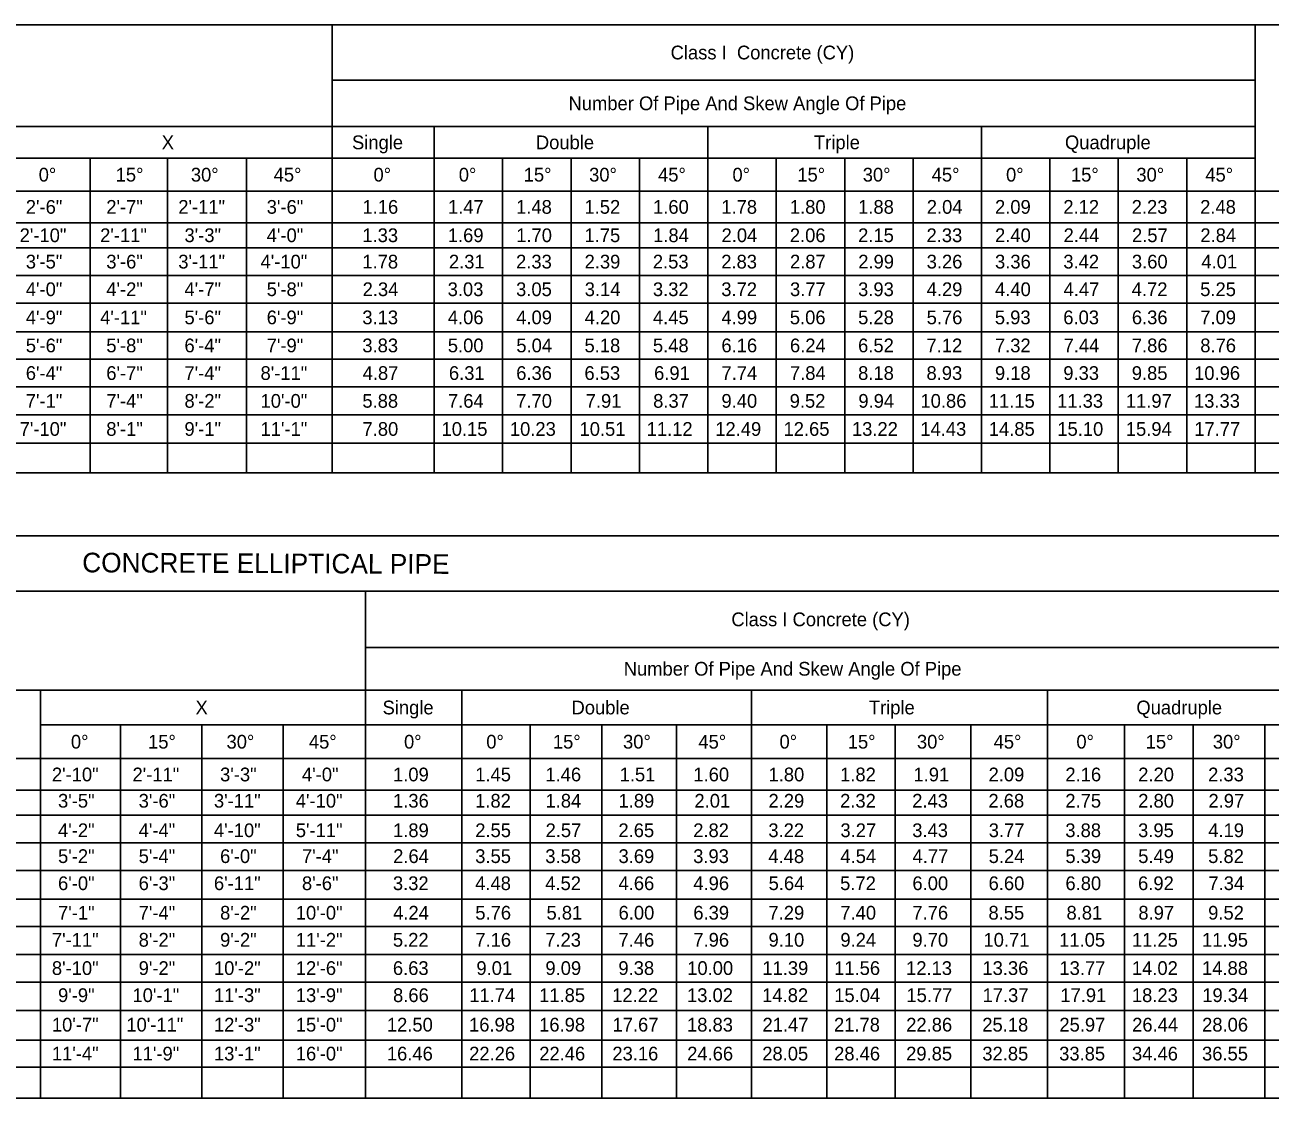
# Model space of a CAD drawing. Extents: x 10029 to 10796, y 10063 to 10519.
# Drawn here: x 10299.4 to 10616.8, y 10063.2 to 10336.7 of the extents above; entities that cross this region are included whole.
import ezdxf

# ---------------------------------------------------------------- set-up
doc = ezdxf.new("R2010")
doc.units = 0
doc.layers.add('Default', color=7, linetype='Continuous')
doc.layers.add('TextStructures', color=7, linetype='Continuous')

msp = doc.modelspace()

# ---------------------------------------------------------------- linework, layer by layer
at = {"layer": 'Default'}
for p, q in [((10039.72, 10336.74), (10681.45, 10336.74)), ((10377.67, 10222.58), (10377.67, 10336.74)), ((10612.98, 10222.58), (10612.98, 10336.74)), ((10377.67, 10322.67), (10612.98, 10322.67)), ((10079.67, 10310.85), (10612.98, 10310.85)), ((10403.72, 10222.58), (10403.72, 10310.85)), ((10473.47, 10222.58), (10473.47, 10310.85)), ((10543.23, 10222.58), (10543.23, 10310.85)), ((10294.71, 10302.76), (10612.98, 10302.76)), ((10315.99, 10222.58), (10315.99, 10302.76)), ((10335.73, 10222.58), (10335.73, 10302.76)), ((10355.84, 10222.58), (10355.84, 10302.76)), ((10421.16, 10222.58), (10421.16, 10302.76)), ((10438.6, 10222.58), (10438.6, 10302.76)), ((10456.04, 10222.58), (10456.04, 10302.76)), ((10490.91, 10222.58), (10490.91, 10302.76)), ((10508.35, 10222.58), (10508.35, 10302.76)), ((10525.79, 10222.58), (10525.79, 10302.76)), ((10560.67, 10222.58), (10560.67, 10302.76)), ((10578.1, 10222.58), (10578.1, 10302.76)), ((10595.54, 10222.58), (10595.54, 10302.76)), ((10039.72, 10294.39), (10681.45, 10294.39)), ((10039.72, 10286.34), (10681.45, 10286.34)), ((10039.72, 10279.92), (10681.45, 10279.92)), ((10039.72, 10272.9), (10681.45, 10272.9)), ((10039.72, 10265.84), (10681.45, 10265.84)), ((10039.72, 10258.56), (10681.45, 10258.56)), ((10039.72, 10251.55), (10681.45, 10251.55)), ((10039.72, 10244.47), (10681.45, 10244.47)), ((10039.72, 10237.36), (10681.45, 10237.36)), ((10039.72, 10230.15), (10681.45, 10230.15)), ((10039.72, 10222.58), (10681.45, 10222.58)), ((10040.76, 10206.56), (10696.75, 10206.56)), ((10040.76, 10192.44), (10696.75, 10192.44)), ((10386.23, 10063.22), (10386.23, 10192.44)), ((10386.23, 10178.05), (10632.55, 10178.05)), ((10084.96, 10167.22), (10632.55, 10167.22)), ((10303.39, 10063.22), (10303.39, 10167.22)), ((10410.73, 10063.22), (10410.73, 10167.22)), ((10484.61, 10063.22), (10484.61, 10167.22)), ((10560.04, 10063.22), (10560.04, 10167.22)), ((10303.39, 10158.32), (10632.55, 10158.32)), ((10323.73, 10063.22), (10323.73, 10158.32)), ((10344.5, 10063.22), (10344.5, 10158.32)), ((10365.25, 10063.22), (10365.25, 10158.32)), ((10428.17, 10063.22), (10428.17, 10158.32)), ((10446.47, 10063.22), (10446.47, 10158.32)), ((10465.46, 10063.22), (10465.46, 10158.32)), ((10503.77, 10063.22), (10503.77, 10158.32)), ((10521.21, 10063.22), (10521.21, 10158.32)), ((10540.54, 10063.22), (10540.54, 10158.32)), ((10579.72, 10063.22), (10579.72, 10158.32)), ((10597.16, 10063.22), (10597.16, 10158.32)), ((10615.46, 10063.22), (10615.46, 10158.32)), ((10040.76, 10149.78), (10696.75, 10149.78)), ((10040.76, 10141.72), (10696.75, 10141.72)), ((10040.76, 10135.31), (10696.75, 10135.31)), ((10040.76, 10128.29), (10696.75, 10128.29)), ((10040.76, 10121.22), (10696.75, 10121.22)), ((10040.76, 10113.95), (10696.75, 10113.95)), ((10040.76, 10106.93), (10696.75, 10106.93)), ((10040.76, 10099.86), (10696.75, 10099.86)), ((10040.76, 10092.75), (10696.75, 10092.75)), ((10040.76, 10085.54), (10696.75, 10085.54)), ((10040.76, 10077.97), (10696.75, 10077.97)), ((10040.76, 10071.08), (10696.75, 10071.08)), ((10040.76, 10063.22), (10696.75, 10063.22))]:
    msp.add_line(p, q, dxfattribs=at)

# ---------------------------------------------------------------- texts
at = {"layer": 'TextStructures'}
for s, p in [('Class I  Concrete (CY)', (10463.98, 10327.96)), ('Number Of Pipe And Skew Angle Of Pipe', (10437.96, 10315.01)), ('X', (10334.25, 10305.06)), ('Single', (10382.76, 10305.06)), ('Double', (10429.64, 10305.06)), ('Triple', (10500.53, 10305.06)), ('Quadruple', (10564.51, 10305.06)), ('0°', (10302.89, 10296.82)), ('15°', (10322.51, 10296.82)), ('30°', (10341.68, 10296.82)), ('45°', (10362.78, 10296.82)), ('0°', (10388.24, 10296.82)), ('0°', (10409.98, 10296.82)), ('15°', (10426.53, 10296.82)), ('30°', (10443.21, 10296.82)), ('45°', (10460.78, 10296.82)), ('0°', (10479.74, 10296.82)), ('15°', (10496.28, 10296.82)), ('30°', (10512.96, 10296.82)), ('45°', (10530.53, 10296.82)), ('0°', (10549.49, 10296.82)), ('15°', (10566.03, 10296.82)), ('30°', (10582.71, 10296.82)), ('45°', (10600.29, 10296.82)), ('Class I Concrete (CY)', (10479.46, 10183.49)), ('Number Of Pipe And Skew Angle Of Pipe', (10452.03, 10170.89)), ('X', (10342.87, 10161.02)), ('Single', (10390.55, 10161.02)), ('Double', (10438.72, 10161.02)), ('Triple', (10514.51, 10161.02)), ('Quadruple', (10582.71, 10161.02)), ('0°', (10311.1, 10152.3)), ('15°', (10330.77, 10152.3)), ('30°', (10350.77, 10152.3)), ('45°', (10371.77, 10152.3)), ('0°', (10396.02, 10152.3)), ('0°', (10416.99, 10152.3)), ('15°', (10433.97, 10152.3)), ('30°', (10451.85, 10152.3)), ('45°', (10471.06, 10152.3)), ('0°', (10491.74, 10152.3)), ('15°', (10509.14, 10152.3)), ('30°', (10526.77, 10152.3)), ('45°', (10546.32, 10152.3)), ('0°', (10567.42, 10152.3)), ('15°', (10585.09, 10152.3)), ('30°', (10602.2, 10152.3))]:
    msp.add_text(s, height=3.5, dxfattribs=at).set_placement(p)
for s, height, rotation, p in [('2\'-6"', 3.5, 0, (10299.6, 10288.61)), ('2\'-7"', 3.5, 0, (10320.12, 10288.61)), ('2\'-11"', 3.5, 0, (10338.47, 10288.61)), ('3\'-6"', 3.5, 0, (10361.01, 10288.61)), ('1.16', 3.5, 0, (10385.43, 10288.61)), ('1.47', 3.5, 0, (10407.22, 10288.61)), ('1.48', 3.5, 0, (10424.59, 10288.61)), ('1.52', 3.5, 0, (10442.02, 10288.61)), ('1.60', 3.5, 0, (10459.5, 10288.61)), ('1.78', 3.5, 0, (10476.9, 10288.61)), ('1.80', 3.5, 0, (10494.38, 10288.61)), ('1.88', 3.5, 0, (10511.78, 10288.61)), ('2.04', 3.5, 0, (10529.28, 10288.61)), ('2.09', 3.5, 0, (10546.68, 10288.61)), ('2.12', 3.5, 0, (10564.09, 10288.61)), ('2.23', 3.5, 0, (10581.52, 10288.61)), ('2.48', 3.5, 0, (10598.97, 10288.61)), ('2\'-10"', 3.5, 0, (10298.03, 10281.38)), ('2\'-11"', 3.5, 0, (10318.55, 10281.38)), ('3\'-3"', 3.5, 0, (10340.05, 10281.38)), ('4\'-0"', 3.5, 0, (10361.01, 10281.38)), ('1.33', 3.5, 0, (10385.39, 10281.38)), ('1.69', 3.5, 0, (10407.18, 10281.38)), ('1.70', 3.5, 0, (10424.62, 10281.38)), ('1.75', 3.5, 0, (10442.03, 10281.38)), ('1.84', 3.5, 0, (10459.52, 10281.38)), ('2.04', 3.5, 0, (10476.96, 10281.38)), ('2.06', 3.5, 0, (10494.37, 10281.38)), ('2.15', 3.5, 0, (10511.78, 10281.38)), ('2.33', 3.5, 0, (10529.21, 10281.38)), ('2.40', 3.5, 0, (10546.69, 10281.38)), ('2.44', 3.5, 0, (10564.15, 10281.38)), ('2.57', 3.5, 0, (10581.6, 10281.38)), ('2.84', 3.5, 0, (10599.03, 10281.38)), ('3\'-5"', 3.5, 0, (10299.6, 10274.66)), ('3\'-6"', 3.5, 0, (10320.12, 10274.66)), ('3\'-11"', 3.5, 0, (10338.47, 10274.66)), ('4\'-10"', 3.5, 0, (10359.44, 10274.66)), ('1.78', 3.5, 0, (10385.4, 10274.66)), ('2.31', 3.5, 0, (10407.46, 10274.66)), ('2.33', 3.5, 0, (10424.58, 10274.66)), ('2.39', 3.5, 0, (10442.05, 10274.66)), ('2.53', 3.5, 0, (10459.45, 10274.66)), ('2.83', 3.5, 0, (10476.89, 10274.66)), ('2.87', 3.5, 0, (10494.41, 10274.66)), ('2.99', 3.5, 0, (10511.81, 10274.66)), ('3.26', 3.5, 0, (10529.25, 10274.66)), ('3.36', 3.5, 0, (10546.68, 10274.66)), ('3.42', 3.5, 0, (10564.09, 10274.66)), ('3.60', 3.5, 0, (10581.57, 10274.66)), ('4.01', 3.5, 0, (10599.28, 10274.66)), ('4\'-0"', 3.5, 0, (10299.6, 10267.62)), ('4\'-2"', 3.5, 0, (10320.12, 10267.62)), ('4\'-7"', 3.5, 0, (10340.05, 10267.62)), ('5\'-8"', 3.5, 0, (10361.01, 10267.62)), ('2.34', 3.5, 0, (10385.46, 10267.62)), ('3.03', 3.5, 0, (10407.14, 10267.62)), ('3.05', 3.5, 0, (10424.59, 10267.62)), ('3.14', 3.5, 0, (10442.09, 10267.62)), ('3.32', 3.5, 0, (10459.46, 10267.62)), ('3.72', 3.5, 0, (10476.89, 10267.62)), ('3.77', 3.5, 0, (10494.41, 10267.62)), ('3.93', 3.5, 0, (10511.77, 10267.62)), ('4.29', 3.5, 0, (10529.25, 10267.62)), ('4.40', 3.5, 0, (10546.69, 10267.62)), ('4.47', 3.5, 0, (10564.16, 10267.62)), ('4.72', 3.5, 0, (10581.52, 10267.62)), ('5.25', 3.5, 0, (10598.98, 10267.62)), ('4\'-9"', 3.5, 0, (10299.6, 10260.45)), ('4\'-11"', 3.5, 0, (10318.55, 10260.45)), ('5\'-6"', 3.5, 0, (10340.05, 10260.45)), ('6\'-9"', 3.5, 0, (10361.01, 10260.45)), ('3.13', 3.5, 0, (10385.39, 10260.45)), ('4.06', 3.5, 0, (10407.18, 10260.45)), ('4.09', 3.5, 0, (10424.62, 10260.45)), ('4.20', 3.5, 0, (10442.06, 10260.45)), ('4.45', 3.5, 0, (10459.47, 10260.45)), ('4.99', 3.5, 0, (10476.93, 10260.45)), ('5.06', 3.5, 0, (10494.37, 10260.45)), ('5.28', 3.5, 0, (10511.78, 10260.45)), ('5.76', 3.5, 0, (10529.25, 10260.45)), ('5.93', 3.5, 0, (10546.64, 10260.45)), ('6.03', 3.5, 0, (10564.08, 10260.45)), ('6.36', 3.5, 0, (10581.56, 10260.45)), ('7.09', 3.5, 0, (10599, 10260.45)), ('5\'-6"', 3.5, 0, (10299.6, 10253.3)), ('5\'-8"', 3.5, 0, (10320.12, 10253.3)), ('6\'-4"', 3.5, 0, (10340.05, 10253.3)), ('7\'-9"', 3.5, 0, (10361.01, 10253.3)), ('3.83', 3.5, 0, (10385.39, 10253.3)), ('5.00', 3.5, 0, (10407.18, 10253.3)), ('5.04', 3.5, 0, (10424.65, 10253.3)), ('5.18', 3.5, 0, (10442.03, 10253.3)), ('5.48', 3.5, 0, (10459.47, 10253.3)), ('6.16', 3.5, 0, (10476.93, 10253.3)), ('6.24', 3.5, 0, (10494.4, 10253.3)), ('6.52', 3.5, 0, (10511.77, 10253.3)), ('7.12', 3.5, 0, (10529.21, 10253.3)), ('7.32', 3.5, 0, (10546.65, 10253.3)), ('7.44', 3.5, 0, (10564.15, 10253.3)), ('7.86', 3.5, 0, (10581.56, 10253.3)), ('8.76', 3.5, 0, (10599, 10253.3)), ('6\'-4"', 3.5, 0, (10299.6, 10246.26)), ('6\'-7"', 3.5, 0, (10320.12, 10246.26)), ('8\'-11"', 3.5, 0, (10359.44, 10246.26)), ('4.87', 3.5, 0, (10385.47, 10246.26)), ('6.31', 3.5, 0, (10407.46, 10246.26)), ('6.36', 3.5, 0, (10424.62, 10246.26)), ('6.53', 3.5, 0, (10442.01, 10246.26)), ('6.91', 3.5, 0, (10459.77, 10246.26)), ('7.84', 3.5, 0, (10494.4, 10246.26)), ('8.18', 3.5, 0, (10511.78, 10246.26)), ('8.93', 3.5, 0, (10529.21, 10246.26)), ('9.18', 3.5, 0, (10546.66, 10246.26)), ('9.33', 3.5, 0, (10564.08, 10246.26)), ('9.85', 3.5, 0, (10581.54, 10246.26)), ('10.96', 3.5, 0, (10597.43, 10246.26)), ('7\'-4"', 3.5, 0, (10340.05, 10246.26)), ('7.74', 3.5, 0, (10476.96, 10246.26)), ('7\'-1"', 3.5, 0, (10299.6, 10239.17)), ('7\'-4"', 3.5, 0, (10320.12, 10239.17)), ('8\'-2"', 3.5, 0, (10340.05, 10239.17)), ('10\'-0"', 3.5, 0, (10359.44, 10239.17)), ('5.88', 3.5, 0, (10385.4, 10239.17)), ('7.64', 3.5, 0, (10407.21, 10239.17)), ('7.70', 3.5, 0, (10424.62, 10239.17)), ('7.91', 3.5, 0, (10442.33, 10239.17)), ('8.37', 3.5, 0, (10459.53, 10239.17)), ('9.40', 3.5, 0, (10476.94, 10239.17)), ('9.52', 3.5, 0, (10494.33, 10239.17)), ('9.94', 3.5, 0, (10511.84, 10239.17)), ('10.86', 3.5, 0, (10527.67, 10239.17)), ('11.15', 3.5, 0, (10545.09, 10239.17)), ('11.33', 3.5, 0, (10562.51, 10239.17)), ('11.97', 3.5, 0, (10580.03, 10239.17)), ('13.33', 3.5, 0, (10597.39, 10239.17)), ('7\'-10"', 3.5, 0, (10298.03, 10232.01)), ('8\'-1"', 3.5, 0, (10320.12, 10232.01)), ('9\'-1"', 3.5, 0, (10340.05, 10232.01)), ('11\'-1"', 3.5, 0, (10359.44, 10232.01)), ('7.80', 3.5, 0, (10385.44, 10232.01)), ('10.15', 3.5, 0, (10405.58, 10232.01)), ('10.23', 3.5, 0, (10423, 10232.01)), ('10.51', 3.5, 0, (10440.76, 10232.01)), ('11.12', 3.5, 0, (10457.88, 10232.01)), ('12.49', 3.5, 0, (10475.36, 10232.01)), ('12.65', 3.5, 0, (10492.77, 10232.01)), ('13.22', 3.5, 0, (10510.2, 10232.01)), ('14.43', 3.5, 0, (10527.63, 10232.01)), ('14.85', 3.5, 0, (10545.09, 10232.01)), ('15.10', 3.5, 0, (10562.56, 10232.01)), ('15.94', 3.5, 0, (10580.02, 10232.01)), ('17.77', 3.5, 0, (10597.47, 10232.01)), ('CONCRETE ELLIPTICAL PIPE', 5, 359.7555, (10313.98, 10197.23)), ('2\'-10"', 3.5, 0, (10306.25, 10143.95)), ('2\'-11"', 3.5, 0, (10326.8, 10143.95)), ('3\'-3"', 3.5, 0, (10349.13, 10143.95)), ('4\'-0"', 3.5, 0, (10370, 10143.95)), ('1.09', 3.5, 0, (10393.22, 10143.95)), ('1.45', 3.5, 0, (10414.17, 10143.95)), ('1.46', 3.5, 0, (10432.06, 10143.95)), ('1.51', 3.5, 0, (10450.98, 10143.95)), ('1.60', 3.5, 0, (10469.78, 10143.95)), ('1.80', 3.5, 0, (10488.94, 10143.95)), ('1.82', 3.5, 0, (10507.19, 10143.95)), ('1.91', 3.5, 0, (10525.89, 10143.95)), ('2.09', 3.5, 0, (10545.03, 10143.95)), ('2.16', 3.5, 0, (10564.62, 10143.95)), ('2.20', 3.5, 0, (10583.18, 10143.95)), ('2.33', 3.5, 0, (10601, 10143.95)), ('3\'-5"', 3.5, 0, (10307.82, 10137.25)), ('3\'-6"', 3.5, 0, (10328.37, 10137.25)), ('3\'-11"', 3.5, 0, (10347.56, 10137.25)), ('4\'-10"', 3.5, 0, (10368.43, 10137.25)), ('1.36', 3.5, 0, (10393.22, 10137.25)), ('1.82', 3.5, 0, (10414.15, 10137.25)), ('1.84', 3.5, 0, (10432.09, 10137.25)), ('1.89', 3.5, 0, (10450.7, 10137.25)), ('2.01', 3.5, 0, (10470.05, 10137.25)), ('2.29', 3.5, 0, (10488.93, 10137.25)), ('2.32', 3.5, 0, (10507.19, 10137.25)), ('2.43', 3.5, 0, (10525.57, 10137.25)), ('2.68', 3.5, 0, (10545, 10137.25)), ('2.75', 3.5, 0, (10564.6, 10137.25)), ('2.80', 3.5, 0, (10583.18, 10137.25)), ('2.97', 3.5, 0, (10601.09, 10137.25)), ('4\'-2"', 3.5, 0, (10307.82, 10129.73)), ('4\'-4"', 3.5, 0, (10328.37, 10129.73)), ('4\'-10"', 3.5, 0, (10347.56, 10129.73)), ('5\'-11"', 3.5, 0, (10368.43, 10129.73)), ('1.89', 3.5, 0, (10393.22, 10129.73)), ('2.55', 3.5, 0, (10414.17, 10129.73)), ('2.57', 3.5, 0, (10432.1, 10129.73)), ('2.65', 3.5, 0, (10450.68, 10129.73)), ('2.82', 3.5, 0, (10469.74, 10129.73)), ('3.22', 3.5, 0, (10488.89, 10129.73)), ('3.27', 3.5, 0, (10507.27, 10129.73)), ('3.43', 3.5, 0, (10525.57, 10129.73)), ('3.77', 3.5, 0, (10545.07, 10129.73)), ('3.88', 3.5, 0, (10564.59, 10129.73)), ('3.95', 3.5, 0, (10583.15, 10129.73)), ('4.19', 3.5, 0, (10601.04, 10129.73)), ('5\'-2"', 3.5, 0, (10307.82, 10123.13)), ('5\'-4"', 3.5, 0, (10328.37, 10123.13)), ('6\'-0"', 3.5, 0, (10349.13, 10123.13)), ('7\'-4"', 3.5, 0, (10370, 10123.13)), ('2.64', 3.5, 0, (10393.25, 10123.13)), ('3.55', 3.5, 0, (10414.17, 10123.13)), ('3.58', 3.5, 0, (10432.03, 10123.13)), ('3.69', 3.5, 0, (10450.7, 10123.13)), ('3.93', 3.5, 0, (10469.73, 10123.13)), ('4.48', 3.5, 0, (10488.9, 10123.13)), ('4.54', 3.5, 0, (10507.26, 10123.13)), ('4.77', 3.5, 0, (10525.66, 10123.13)), ('5.24', 3.5, 0, (10545.06, 10123.13)), ('5.39', 3.5, 0, (10564.62, 10123.13)), ('5.49', 3.5, 0, (10583.18, 10123.13)), ('5.82', 3.5, 0, (10601.01, 10123.13)), ('6\'-0"', 3.5, 0, (10307.82, 10116.23)), ('6\'-3"', 3.5, 0, (10328.37, 10116.23)), ('6\'-11"', 3.5, 0, (10347.56, 10116.23)), ('8\'-6"', 3.5, 0, (10370, 10116.23)), ('3.32', 3.5, 0, (10393.18, 10116.23)), ('4.48', 3.5, 0, (10414.16, 10116.23)), ('4.52', 3.5, 0, (10432.02, 10116.23)), ('4.66', 3.5, 0, (10450.7, 10116.23)), ('4.96', 3.5, 0, (10469.77, 10116.23)), ('5.64', 3.5, 0, (10488.96, 10116.23)), ('5.72', 3.5, 0, (10507.19, 10116.23)), ('6.00', 3.5, 0, (10525.62, 10116.23)), ('6.60', 3.5, 0, (10545.04, 10116.23)), ('6.80', 3.5, 0, (10564.63, 10116.23)), ('6.92', 3.5, 0, (10583.14, 10116.23)), ('7.34', 3.5, 0, (10601.08, 10116.23)), ('7\'-1"', 3.5, 0, (10307.82, 10108.71)), ('7\'-4"', 3.5, 0, (10328.37, 10108.71)), ('8\'-2"', 3.5, 0, (10349.13, 10108.71)), ('10\'-0"', 3.5, 0, (10368.43, 10108.71)), ('4.24', 3.5, 0, (10393.25, 10108.71)), ('5.76', 3.5, 0, (10414.19, 10108.71)), ('5.81', 3.5, 0, (10432.34, 10108.71)), ('6.00', 3.5, 0, (10450.71, 10108.71)), ('6.39', 3.5, 0, (10469.77, 10108.71)), ('7.29', 3.5, 0, (10488.93, 10108.71)), ('7.40', 3.5, 0, (10507.24, 10108.71)), ('7.76', 3.5, 0, (10525.61, 10108.71)), ('8.55', 3.5, 0, (10545.01, 10108.71)), ('8.81', 3.5, 0, (10564.9, 10108.71)), ('8.97', 3.5, 0, (10583.22, 10108.71)), ('9.52', 3.5, 0, (10601.01, 10108.71)), ('7\'-11"', 3.5, 0, (10306.25, 10101.81)), ('8\'-2"', 3.5, 0, (10328.37, 10101.81)), ('9\'-2"', 3.5, 0, (10349.13, 10101.81)), ('11\'-2"', 3.5, 0, (10368.43, 10101.81)), ('5.22', 3.5, 0, (10393.18, 10101.81)), ('7.16', 3.5, 0, (10414.19, 10101.81)), ('7.23', 3.5, 0, (10432.02, 10101.81)), ('7.46', 3.5, 0, (10450.7, 10101.81)), ('7.96', 3.5, 0, (10469.77, 10101.81)), ('9.10', 3.5, 0, (10488.94, 10101.81)), ('9.24', 3.5, 0, (10507.26, 10101.81)), ('9.70', 3.5, 0, (10525.62, 10101.81)), ('10.71', 3.5, 0, (10543.74, 10101.81)), ('11.05', 3.5, 0, (10563.03, 10101.81)), ('11.25', 3.5, 0, (10581.58, 10101.81)), ('11.95', 3.5, 0, (10599.45, 10101.81)), ('8\'-10"', 3.5, 0, (10306.25, 10094.6)), ('9\'-2"', 3.5, 0, (10328.37, 10094.6)), ('10\'-2"', 3.5, 0, (10347.56, 10094.6)), ('12\'-6"', 3.5, 0, (10368.43, 10094.6)), ('6.63', 3.5, 0, (10393.18, 10094.6)), ('9.01', 3.5, 0, (10414.47, 10094.6)), ('9.09', 3.5, 0, (10432.06, 10094.6)), ('9.38', 3.5, 0, (10450.67, 10094.6)), ('10.00', 3.5, 0, (10468.21, 10094.6)), ('11.39', 3.5, 0, (10487.36, 10094.6)), ('11.56', 3.5, 0, (10505.66, 10094.6)), ('12.13', 3.5, 0, (10524, 10094.6)), ('13.36', 3.5, 0, (10543.46, 10094.6)), ('13.77', 3.5, 0, (10563.09, 10094.6)), ('14.02', 3.5, 0, (10581.57, 10094.6)), ('14.88', 3.5, 0, (10599.45, 10094.6)), ('9\'-9"', 3.5, 0, (10307.82, 10087.7)), ('10\'-1"', 3.5, 0, (10326.8, 10087.7)), ('11\'-3"', 3.5, 0, (10347.56, 10087.7)), ('13\'-9"', 3.5, 0, (10368.43, 10087.7)), ('8.66', 3.5, 0, (10393.22, 10087.7)), ('11.74', 3.5, 0, (10412.65, 10087.7)), ('11.85', 3.5, 0, (10430.46, 10087.7)), ('12.22', 3.5, 0, (10449.09, 10087.7)), ('13.02', 3.5, 0, (10468.16, 10087.7)), ('14.82', 3.5, 0, (10487.32, 10087.7)), ('15.04', 3.5, 0, (10505.69, 10087.7)), ('15.77', 3.5, 0, (10524.09, 10087.7)), ('17.37', 3.5, 0, (10543.5, 10087.7)), ('17.91', 3.5, 0, (10563.33, 10087.7)), ('18.23', 3.5, 0, (10581.57, 10087.7)), ('19.34', 3.5, 0, (10599.51, 10087.7)), ('10\'-7"', 3.5, 0, (10306.25, 10080.18)), ('10\'-11"', 3.5, 0, (10325.23, 10080.18)), ('12\'-3"', 3.5, 0, (10347.56, 10080.18)), ('15\'-0"', 3.5, 0, (10368.43, 10080.18)), ('12.50', 3.5, 0, (10391.65, 10080.18)), ('16.98', 3.5, 0, (10412.59, 10080.18)), ('16.98', 3.5, 0, (10430.46, 10080.18)), ('17.67', 3.5, 0, (10449.17, 10080.18)), ('18.83', 3.5, 0, (10468.16, 10080.18)), ('21.47', 3.5, 0, (10487.4, 10080.18)), ('21.78', 3.5, 0, (10505.63, 10080.18)), ('22.86', 3.5, 0, (10524.04, 10080.18)), ('25.18', 3.5, 0, (10543.43, 10080.18)), ('25.97', 3.5, 0, (10563.09, 10080.18)), ('26.44', 3.5, 0, (10581.64, 10080.18)), ('28.06', 3.5, 0, (10599.47, 10080.18)), ('11\'-4"', 3.5, 0, (10306.25, 10072.81)), ('11\'-9"', 3.5, 0, (10326.8, 10072.81)), ('13\'-1"', 3.5, 0, (10347.56, 10072.81)), ('16\'-0"', 3.5, 0, (10368.43, 10072.81)), ('16.46', 3.5, 0, (10391.65, 10072.81)), ('22.26', 3.5, 0, (10412.62, 10072.81)), ('22.46', 3.5, 0, (10430.49, 10072.81)), ('23.16', 3.5, 0, (10449.13, 10072.81)), ('24.66', 3.5, 0, (10468.2, 10072.81)), ('28.05', 3.5, 0, (10487.34, 10072.81)), ('28.46', 3.5, 0, (10505.66, 10072.81)), ('29.85', 3.5, 0, (10524.02, 10072.81)), ('32.85', 3.5, 0, (10543.44, 10072.81)), ('33.85', 3.5, 0, (10563.03, 10072.81)), ('34.46', 3.5, 0, (10581.6, 10072.81)), ('36.55', 3.5, 0, (10599.45, 10072.81))]:
    msp.add_text(s, height=height, rotation=rotation, dxfattribs=at).set_placement(p)

doc.saveas('drawing.dxf')
